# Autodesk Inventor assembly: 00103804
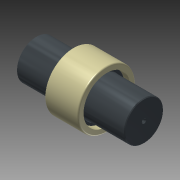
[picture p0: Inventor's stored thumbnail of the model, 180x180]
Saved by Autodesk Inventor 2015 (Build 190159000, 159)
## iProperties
Created: 2018-06
Part Number: 00103804
Document SubType Name: Assembly
Designer: stagistacad
Author: stagistacad
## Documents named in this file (3)
- C:\Users\stagistacad\Desktop\00103804.iam
- C:\Users\stagistacad\Desktop\00103810.ipt
- C:\Users\stagistacad\Desktop\00103840.ipt
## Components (3 placed, 2 different names)
1. 00103810:1 — Coincidente:4, Coincidente:5, Coincidente:6, Coincidente:7
2. 00103840:1 — Coincidente:4, Coincidente:5
3. 00103840:2 — Coincidente:6, Coincidente:7
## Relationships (4: Mate 4)
- Coincidente:4 [Mate]: 00103810:1 ↔ 00103840:1
- Coincidente:5 [Mate]: 00103810:1 ↔ 00103840:1
- Coincidente:6 [Mate]: 00103810:1 ↔ 00103840:2
- Coincidente:7 [Mate]: 00103810:1 ↔ 00103840:2
